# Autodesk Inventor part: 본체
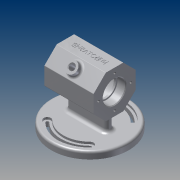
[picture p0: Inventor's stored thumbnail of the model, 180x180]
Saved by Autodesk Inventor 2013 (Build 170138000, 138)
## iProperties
Created: 2017-06
Part Number: 본체
Material: 알루미늄 6061
Document SubType Name: Modeling
Designer: Administrator
Density: 2.71 g/cm^3
Mass: 562.521 g
Surface Area: 565.55 cm^2
Volume: 207.572 cm^3
Author: Administrator
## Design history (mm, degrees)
sketch "스케치2" dims "d4" = 60
  geometry: L1 (30, -12.426)-(12.426, -30); L2 (12.426, -30)-(-12.426, -30); L3 (-12.426, -30)-(-30, -12.426); L4 (-30, -12.426)-(-30, 12.426); L5 (-30, 12.426)-(-12.426, 30); L6 (-12.426, 30)-(12.426, 30); L7 (12.426, 30)-(30, 12.426); L8 (30, 12.426)-(30, -12.426); 4 further points
  constraints: 16 end point, 2 coincident, 1 horizontal alignment, 1 midpoint, 19 other
  dimensions: "d5" = 17.57359 horizontal distance of L6.end L7.end
extrude "돌출2" new body sketch "스케치2" distance "d6" = 70; taper "d7" = 0 deg
sketch "스케치3"
  geometry: L1 (0, 0)-(12, 0); L2 (12, 0)-(12, 16); L3 (12, 16)-(0, 16); L4 (0, 16)-(0, 0); L5 (12, 0)-(15, 0); L6 (15, 0)-(15, 14); L7 (15, 14)-(12, 14); L8 (12, 14)-(12, 0); L9 (15, 0)-(55, 0); L10 (55, 0)-(55, 25); L11 (55, 25)-(15, 25); L12 (15, 25)-(15, 0); L13 (55, 0)-(58, 0); L14 (58, 0)-(58, 14); L15 (58, 14)-(55, 14); L16 (55, 14)-(55, 0); L17 (58, 0)-(70, 0); L18 (70, 0)-(70, 16); L19 (70, 16)-(58, 16); L20 (58, 16)-(58, 0); L21 (15, 0)-(55, 0)
  constraints: 42 end point, 11 equal length, 5 horizontal, 5 perpendicular
  dimensions: "d8" = 16 distance between parallel lines of L1 L3; "d10" = 12 distance of L2.end L3.end; "d11" = 3 distance of L6.end L7.end; "d12" = 14 distance between parallel lines of L5 L7; "d13" = 25 distance between parallel lines of L9 L11; "d14" = 40 distance of L10.end L11.end; "d15" = 3 distance of L14.end L15.end; "d16" = 14 distance between parallel lines of L13 L15; "d17" = 12 distance of L18.end L19.end; "d18" = 16 distance between parallel lines of L19 L17
revolve "회전1" sketch "스케치3" stored, may be unused: angle "d19" = 90 deg
chamfer "모따기1" distance "d20" = 1; stored, may be unused: second distance "d21" = 2, angle "d22" = 45 deg
fillet "모깎기1" dims "d23" = 0.3
fillet "모깎기2" dims "d24" = 3
sketch "스케치4"
  geometry: C1 r 17 at (0, 0) reference; 1 further point
  constraints: 1 vertical alignment
  dimensions: "d25" = 23 distance of point (0, 23) C1.centre
hole "구멍1" sketch "스케치4" at (0, 23) diameter "d26" = 3.242; stored, may be unused: countersink angle "d30" = 90 deg, drill point angle "d32" = 118 deg; dims "d27" = 8, "d28" = 4, "d29" = 2, "d31" = 10
node "작업 평면1"
sketch "스케치5"
  geometry: L1 (0, 42.426)-(70, 42.426) reference; C1 r 8 at (35, 12.426); 1 further point
  constraints: 1 centre point
  dimensions: "d36" = 16 diameter of C1; "d37" = 35 distance of point (0, 12.426) C1.centre; "d38" = 30 distance from line of C1.centre L1
extrude "돌출3" join sketch "스케치5" distance "d39" = 7; taper "d40" = 0 deg
sketch "스케치6"
  geometry: C1 r 8 at (0, 0) reference; C2 r 4 at (0, 0); 1 further point
  constraints: 1 centre point, 1 coincident
  dimensions: "d41" = 8 diameter of C2
extrude "돌출4" cut sketch "스케치6" distance "d42" = 40; taper "d43" = 0 deg
fillet "모깎기3" dims "d44" = 3
chamfer "모따기2" distance "d45" = 1; stored, may be unused: second distance "d46" = 2, angle "d47" = 45 deg
node "작업 평면2"
sketch "스케치7" dims "d49" = 110
  geometry: L1 (0, -30)-(-70, -30) reference; L2 (0, 30)-(-70, 30) reference; L3 (-70, -12.426)-(-70, 12.426) reference; L4 (-70, -30)-(-70, -12.426) reference; L5 (0, -12.426)-(0, -30) reference; 3 further points
  constraints: 2 vertical alignment, 1 horizontal alignment, 2 other
  dimensions: "d51" = 35 distance of point (-35, 0) point (0, 0)
extrude "돌출5" join sketch "스케치7" distance "d52" = 10; taper "d53" = 0 deg
fillet "모깎기4" dims "d54" = 3
sketch "스케치8"
  geometry: L1 (0, 0)-(0, 74.505); L2 (0, 0)-(-54.26, 54.26); L3 (0, 0)-(48.488, 48.488); C1 r 52 at (0, 0) reference; A1 r 48 centre (0, 0) between (33.941, 33.941) and (-33.941, 33.941); A2 r 38 centre (0, 0) between (26.87, 26.87) and (-26.87, 26.87); A3 r 5 centre (30.406, 30.406) between (26.87, 26.87) and (33.941, 33.941); A4 r 5 centre (-30.406, 30.406) between (-33.941, 33.941) and (-26.87, 26.87); 1 further point
  constraints: 8 point on circle, 6 end point, 4 centre point, 4 point on line, 2 coincident, 2 tangent, 1 vertical
  dimensions: "d55" = 96 diameter of A1; "d56" = 76 diameter of A2; "d57" = 45 deg angle of L3 L1; "d58" = 45 deg angle of L1 L2; "d60" = 5 radius of A3; "d61" = 48.48819 distance from line of L3.end L1; "d62" = 52.68307 distance from line of L1.end L3; "d63" = 76.73489 distance from line of L2.end L3
extrude "돌출6" cut sketch "스케치8" distance "d64" = 3; taper "d65" = 0 deg
sketch "스케치9"
  geometry: A1 r 5 centre (30.406, 30.406) between (26.87, 26.87) and (33.941, 33.941) reference; A2 r 48 centre (0, 0) between (33.941, 33.941) and (-33.941, 33.941) reference; A3 r 5 centre (-30.406, 30.406) between (-33.941, 33.941) and (-26.87, 26.87) reference; A4 r 2 centre (-30.406, 30.406) between (-31.82, 31.82) and (-28.991, 28.991); A5 r 2 centre (30.406, 30.406) between (28.991, 28.991) and (31.82, 31.82); A6 r 41 centre (0, 0) between (28.991, 28.991) and (-28.991, 28.991); A7 r 43 centre (0, 0) between (31.787, 28.959) and (-31.787, 28.959); A8 r 45 centre (0, 0) between (31.82, 31.82) and (-31.82, 31.82); 1 further point
  constraints: 12 point on circle, 5 centre point, 3 coincident
  dimensions: "d67" = 4 diameter of A4; "d68" = 4 diameter of A5; "d69" = 41 radius of A6; "d70" = 43 radius of A7; "d71" = 45 radius of A8
extrude "돌출7" cut sketch "스케치9" distance "d72" = 7; taper "d73" = 0 deg
sketch "스케치10"
  geometry: L1 (-24, 5)-(24, 5); L2 (24, 5)-(24, -5); L3 (24, -5)-(-24, -5); L4 (-24, -5)-(-24, 5); A1 r 48 centre (0, 0) between (-33.941, -33.941) and (33.941, -33.941) reference; A2 r 5 centre (24, 0) between (24, -5) and (24, 5); A3 r 5 centre (-24, 0) between (-24, 5) and (-24, -5); 3 further points
  constraints: 8 end point, 4 point on circle, 4 tangent, 2 centre point, 2 midpoint, 2 parallel, 1 horizontal, 1 horizontal alignment, 1 perpendicular, 1 vertical alignment
  dimensions: "d74" = 48 distance between parallel lines of L4 L2; "d76" = 10 distance of L3.end L1.start
extrude "돌출8" join sketch "스케치10" stored distance "d77" = 7; taper "d78" = 0 deg
fillet "모깎기5" dims "d79" = 5
fillet "모깎기6" dims "d80" = 1
node "작업 평면3"
sketch "스케치11"
  geometry: L1 (10.113, 16.755)-(59.887, 16.755); L2 (59.887, 16.755)-(59.887, 6.684); L3 (59.887, 6.684)-(10.113, 6.684); L4 (10.113, 6.684)-(10.113, 16.755); L5 (0, 24.731)-(0, 41.719) reference; L6 (0, 41.719)-(70, 41.719) reference; L7 (70, 41.719)-(70, 24.731) reference; 3 further points
  constraints: 2 midpoint, 1 parallel, 2 other
  dimensions: "d82" = 35 distance from line of point (35, 16.755) L5; "d83" = 30 distance from line of L6 point (59.887, 11.719); "d84" = 24.96431 distance from line of L6 point (35, 16.755); "d85" = 10.11262 distance from line of L7 point (59.887, 11.719)
feature "엠보싱1" sketch "스케치11" dims "d8" = 16, "d10" = 12, "d11" = 3, "d12" = 14, "d13" = 25, "d14" = 40, "d15" = 3, "d16" = 14, "d17" = 12, "d18" = 16, "d86" = 0.5, "d87" = 0
node "솔리드2"
pattern_circular "원형 패턴1" dims angle "d34" = 360 deg
mirror "대칭1"
mirror "대칭2"
other parameters: "d48" = -62, "d66" = 86, "d81" = 0.5
